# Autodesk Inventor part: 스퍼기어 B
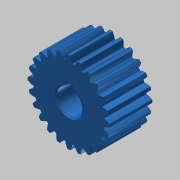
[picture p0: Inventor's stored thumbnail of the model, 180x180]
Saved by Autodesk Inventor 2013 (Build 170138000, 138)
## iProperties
Created: 2020-04
Part Number: 스퍼기어 B
Material: Steel
Document SubType Name: Modeling
Designer: mduedu
Categories: <?xml version="1.0" encoding="UTF-16"?> <MemberInstance><Categories><FamilyTemplate><FamilyTemplateParameter ValueType="xs:double" Id="1" ObjectReferenceKey="da
Density: 7.85 g/cm^3
Mass: 140.141 g
Surface Area: 65.0479 cm^2
Volume: 17.8523 cm^3
CustomPartVersion: 1
Author: mduedu
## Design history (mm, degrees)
sketch "Sketch1"
  geometry: C1 r 19.2 at (0, 0)
  constraints: 1 centre point
  dimensions: "d0" = 38.4 diameter of C1 (= da_da)
extrude "Extrusion1" new body sketch "Sketch1" distance "d1" = 20 (= da_b); taper "d2" = 0 deg
workplane "Work Plane2"
sketch "Sketch2"
  geometry: C1 r 19.2 at (0, 0) reference; C2 r 18 at (0, 0)
  constraints: 1 centre point, 1 coincident
  dimensions: "d3" = 36 diameter of C2 (= da_dw)
feature "피치 지름" sketch "Sketch2" dims "d4" = 10, "d5" = 0
workplane "Work Plane8"
workplane "Work Plane9"
feature "스퍼 기어" dims "da_b" = 20, "da_d" = 36, "da_aw" = 45, "da_da" = 38.4, "da_df" = 33.129, "da_dw" = 36, angle "da_beta" = 0 deg, "da_lefttooth" = 0, "da_righttooth" = 0
sketch "스케치3"
  geometry: L1 (-2, 5.657)-(2, 5.657); L2 (2, 5.657)-(2, 7.8); L3 (2, 7.8)-(-2, 7.8); L4 (-2, 7.8)-(-2, 5.657); A1 r 6 centre (0, 0) between (-2, 5.657) and (2, 5.657); 1 further point
  constraints: 8 end point, 2 parallel, 2 point on circle, 1 centre point, 1 coincident, 1 horizontal, 1 perpendicular
  dimensions: "d49" = 12 diameter of A1; "d51" = 4 distance of L2.end L3.end; "d52" = 13.8 dimension on A1 L3
extrude "돌출2" cut sketch "스케치3" stored distance "d53" = 10; taper "d54" = 0 deg
chamfer "모따기1" distance "d55" = 0.5; stored, may be unused: second distance "d56" = 2, angle "d57" = 45 deg
body "Solid1"
body "Srf1"
other parameters: "d16" = 45 (= da_aw), "d17" = 0, "d34" = 7.5 deg (computed from da_z), "d39" = 0, "d41" = 0, "d43" = 45 (= da_aw), "d46" = 45 (= da_aw), "d47" = 0, "d48" = 0
